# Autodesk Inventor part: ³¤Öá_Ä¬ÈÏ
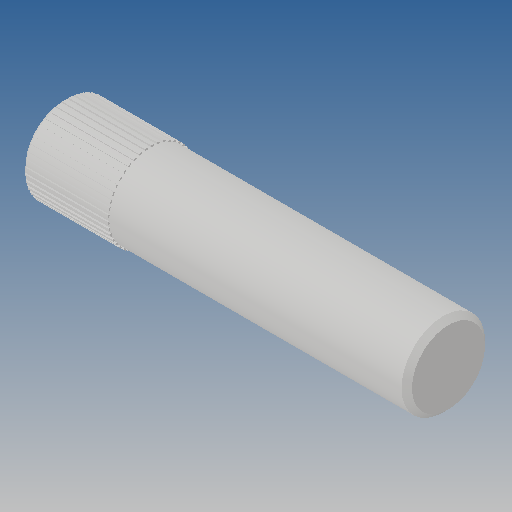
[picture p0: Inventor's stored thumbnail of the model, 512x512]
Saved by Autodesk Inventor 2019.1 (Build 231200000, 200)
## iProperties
Created: 2012-10
Part Number: ³¤Öá_Ä¬ÈÏ
Material: Ogólny
Document SubType Name: Modeling
Designer: CADENGINEERING4
Density: 1 g/cm^3
Appearance: Domyślna
Author: CADENGINEERING4
Revision Number: ÈÎºÎ
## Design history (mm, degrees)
feature "NONE"
node "Bryła1"
